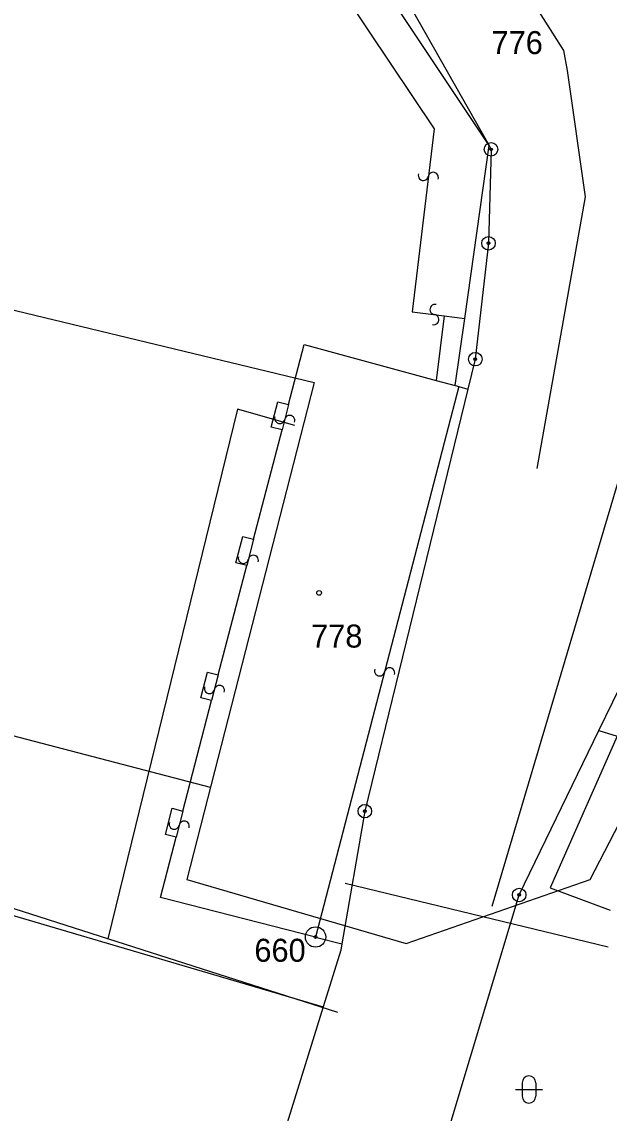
# Model space of a CAD drawing. Extents: x -469926 to -462499, y -1098642 to -1092733.
# Drawn here: x -465590.7 to -465547.2, y -1095008.2 to -1094927.6 of the extents above; entities that cross this region are included whole.
import ezdxf

# ---------------------------------------------------------------- set-up
doc = ezdxf.new("R2010")
doc.units = 0
for name, color, linetype in [('Vrstva 1', 7, 'Continuous'), ('Vrstva 14', 7, 'Continuous'), ('Vrstva 16', 7, 'Continuous'), ('Vrstva 24', 7, 'Continuous'), ('Vrstva 25', 7, 'Continuous'), ('Vrstva 4', 7, 'Continuous'), ('Vrstva 50', 7, 'Continuous'), ('Vrstva 51', 7, 'Continuous'), ('Vrstva 8', 7, 'Continuous')]:
    doc.layers.add(name, color=color, linetype=linetype)

msp = doc.modelspace()

# ---------------------------------------------------------------- linework, layer by layer
at = {"layer": 'Vrstva 1'}
for p, q in [((-465550.58, -1094929.69), (-465565.02, -1094906.69)), ((-465562.83, -1094924.83), (-465556.1, -1094936.7)), ((-465550.3, -1094931.15), (-465550.58, -1094929.69)), ((-465548.96, -1094940.5), (-465550.3, -1094931.15)), ((-465555.95, -1094936.99), (-465556.14, -1094943.93)), ((-465556.1, -1094936.7), (-465555.95, -1094936.99)), ((-465552.55, -1094960.58), (-465548.96, -1094940.5)), ((-465556.14, -1094943.93), (-465557.12, -1094952.5)), ((-465570.93, -1094955.85), (-465569.77, -1094951.41)), ((-465569.77, -1094951.41), (-465560.01, -1094954.07)), ((-465557.12, -1094952.5), (-465557.66, -1094954.71)), ((-465560.01, -1094954.07), (-465558.6, -1094954.45)), ((-465557.66, -1094954.71), (-465565.29, -1094985.9)), ((-465558.6, -1094954.45), (-465558.33, -1094954.52)), ((-465558.33, -1094954.52), (-465557.66, -1094954.71)), ((-465572.21, -1094957.52), (-465571.72, -1094955.65)), ((-465571.72, -1094955.65), (-465570.93, -1094955.85)), ((-465571.41, -1094957.73), (-465572.21, -1094957.52)), ((-465573.52, -1094965.81), (-465571.41, -1094957.73)), ((-465547.97, -1094979.93), (-465537.51, -1094958.34)), ((-465574.82, -1094967.54), (-465574.31, -1094965.61)), ((-465574.31, -1094965.61), (-465573.52, -1094965.81)), ((-465576.13, -1094975.83), (-465574.02, -1094967.75)), ((-465574.02, -1094967.75), (-465574.82, -1094967.54)), ((-465577.41, -1094977.52), (-465576.92, -1094975.63)), ((-465576.92, -1094975.63), (-465576.13, -1094975.83)), ((-465576.62, -1094977.73), (-465577.41, -1094977.52)), ((-465578.74, -1094985.89), (-465576.62, -1094977.73)), ((-465553.87, -1094992.09), (-465547.97, -1094979.93)), ((-465547.97, -1094979.93), (-465546.62, -1094980.35)), ((-465546.62, -1094980.35), (-465551.58, -1094991.57)), ((-465618.7, -1094985.52), (-465568.37, -1095000.37)), ((-465580.04, -1094987.62), (-465579.54, -1094985.69)), ((-465579.54, -1094985.69), (-465578.74, -1094985.89)), ((-465565.29, -1094985.9), (-465566.98, -1094995.7)), ((-465580.41, -1094992.28), (-465579.25, -1094987.83)), ((-465579.25, -1094987.83), (-465580.04, -1094987.62)), ((-465572.88, -1095055.23), (-465553.87, -1094992.09)), ((-465551.58, -1094991.57), (-465547.15, -1094993.22)), ((-465568.93, -1094995.2), (-465580.41, -1094992.28)), ((-465568.93, -1094995.2), (-465566.98, -1094995.7)), ((-465567.07, -1094996.17), (-465568.37, -1095000.37)), ((-465566.98, -1094995.7), (-465567.07, -1094996.17)), ((-465568.37, -1095000.37), (-465573.44, -1095016.72))]:
    msp.add_line(p, q, dxfattribs=at)
at = {"layer": 'Vrstva 14'}
for p, q in [((-465593.11, -1094948.433), (-465569.032, -1094954.209)), ((-465569.032, -1094954.209), (-465578.454, -1094990.962)), ((-465548.618, -1094990.962), (-465532.392, -1094959.459)), ((-465576.707, -1094984.146), (-465600.587, -1094977.936)), ((-465578.454, -1094990.962), (-465562.227, -1094995.687)), ((-465562.227, -1094995.687), (-465548.618, -1094990.962))]:
    msp.add_line(p, q, dxfattribs=at)
at = {"layer": 'Vrstva 16'}
for p, q in [((-465574.694, -1094956.18), (-465584.303, -1094995.336)), ((-465570.461, -1094957.393), (-465574.694, -1094956.18)), ((-465567.282, -1095000.775), (-465604.328, -1094988.937))]:
    msp.add_line(p, q, dxfattribs=at)
at = {"layer": 'Vrstva 24'}
for centre, radius in [((-465555.95, -1094936.99), 0.5), ((-465555.95, -1094936.99), 0.1), ((-465556.14, -1094943.93), 0.5), ((-465556.14, -1094943.93), 0.1), ((-465557.12, -1094952.5), 0.5), ((-465557.12, -1094952.5), 0.1), ((-465565.29, -1094985.9), 0.5), ((-465565.29, -1094985.9), 0.1), ((-465553.87, -1094992.09), 0.5), ((-465553.87, -1094992.09), 0.1), ((-465568.93, -1094995.2), 0.75), ((-465568.93, -1094995.2), 0.1)]:
    msp.add_circle(centre, radius, dxfattribs=at)
at = {"layer": 'Vrstva 25'}
for p, q in [((-465554.15, -1095006.47), (-465552.15, -1095006.47)), ((-465553.65, -1095005.97), (-465553.65, -1095006.97)), ((-465552.65, -1095005.97), (-465552.65, -1095006.97))]:
    msp.add_line(p, q, dxfattribs=at)
msp.add_circle((-465568.67, -1094969.77), 0.175, dxfattribs=at)
for centre, start, end in [((-465553.151, -1095005.971), 0, 180), ((-465553.151, -1095006.971), 180, 0)]:
    msp.add_arc(centre, 0.5, start, end, dxfattribs=at)
at = {"layer": 'Vrstva 4'}
for p, q in [((-465556.1, -1094936.7), (-465582.18, -1094897.58)), ((-465583.53, -1094900.6), (-465560.17, -1094935.47)), ((-465560.17, -1094935.47), (-465561.79, -1094948.99)), ((-465557.9, -1094949.49), (-465556.1, -1094936.7)), ((-465561.79, -1094948.99), (-465559.41, -1094949.29)), ((-465559.41, -1094949.29), (-465560.01, -1094954.07)), ((-465559.41, -1094949.29), (-465557.9, -1094949.49)), ((-465558.6, -1094954.45), (-465557.9, -1094949.49)), ((-465558.33, -1094954.52), (-465568.93, -1094995.2)), ((-465570.93, -1094955.85), (-465571.41, -1094957.73)), ((-465573.52, -1094965.81), (-465574.02, -1094967.75)), ((-465576.13, -1094975.83), (-465576.62, -1094977.73)), ((-465578.74, -1094985.89), (-465579.25, -1094987.83))]:
    msp.add_line(p, q, dxfattribs=at)
at = {"layer": 'Vrstva 51'}
for centre, radius, start, end in [((-465560.961, -1094938.916), 0.376, 161.99036, 348.30149), ((-465560.222, -1094939.064), 0.377, 341.31432, 168.97753), ((-465560.093, -1094948.825), 0.376, 76.40036, 262.71149), ((-465560.184, -1094949.572), 0.377, 255.72432, 83.38753), ((-465570.842, -1094957.026), 0.377, 341.31432, 168.97753), ((-465571.58, -1094956.877), 0.376, 161.99036, 348.30149), ((-465574.27, -1094967.214), 0.376, 161.99036, 348.30149), ((-465573.532, -1094967.362), 0.377, 341.31432, 168.97753), ((-465564.193, -1094975.53), 0.376, 161.99036, 348.30149), ((-465563.455, -1094975.678), 0.377, 341.31432, 168.97753), ((-465576.777, -1094976.832), 0.376, 161.99036, 348.30149), ((-465576.038, -1094976.98), 0.377, 341.31432, 168.97753), ((-465579.384, -1094986.862), 0.376, 161.99036, 348.30149), ((-465578.646, -1094987.01), 0.377, 341.31432, 168.97753)]:
    msp.add_arc(centre, radius, start, end, dxfattribs=at)
at = {"layer": 'Vrstva 8'}
for p, q in [((-465555.861, -1094992.932), (-465490.935, -1094773.91)), ((-465566.731, -1094991.225), (-465547.279, -1094995.934))]:
    msp.add_line(p, q, dxfattribs=at)

# ---------------------------------------------------------------- texts
at = {"layer": 'Vrstva 50'}
for s, p in [('776', (-465555.915, -1094929.95)), ('778', (-465569.257, -1094973.81)), ('660', (-465573.453, -1094997.03))]:
    msp.add_text(s, height=1.7, dxfattribs=at).set_placement(p)

doc.saveas('drawing.dxf')
